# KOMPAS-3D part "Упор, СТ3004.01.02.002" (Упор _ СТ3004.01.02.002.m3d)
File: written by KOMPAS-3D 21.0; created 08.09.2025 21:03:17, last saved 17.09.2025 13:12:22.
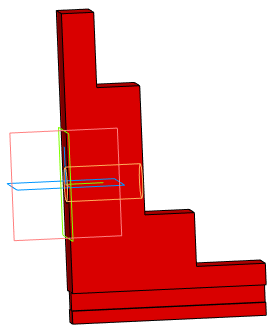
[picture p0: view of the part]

Document properties: Полное имя файла: C:\Users\Lutik\Yandex.Disk\Документы\Новая папка\Стапель №2\Стапель _ СТ3004.00.00.000\Опора _ СТ3004.01.00.000\3D\Кронштейн _ СТ3004.01.02.000\Упор _ СТ3004.01.02.002.m3d

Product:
- Part/product: Упор  | designation СТ3004.01.02.002
    Материал: Сталь 45  ГОСТ 1050-2013 (density 7810 kg/m3)
    Масса: 1.036373
    Форматы листов документа: A3

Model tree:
1. Эскиз:1
2. Элемент выдавливания:1
     Расстояние 1 = 90
3. Эскиз:2  (with: Элемент выдавливания:1)
4. Элемент выдавливания:2
     Расстояние 2 = 25
5. Эскиз:3  (with: Элемент выдавливания:1)
6. Элемент выдавливания:3
7. Условное изображение резьбы:1  (with: Элемент выдавливания:3)  (labels: M16; cil0_24705-2004 coarse)
     Длина резьбы = 35; Шаг резьбы = 2; Номинальный диаметр резьбы = 16
8. Подгонка:1  (with: Элемент выдавливания:3)
9. Фаска:1  (with: Элемент выдавливания:3)  (labels: Сталь 45  ГОСТ 1050-2013)
     Угол = 45; Длина 1 = 2; Длина 2 = 2

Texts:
  СТ3004.01.02.002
